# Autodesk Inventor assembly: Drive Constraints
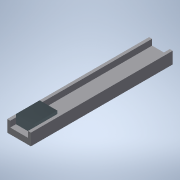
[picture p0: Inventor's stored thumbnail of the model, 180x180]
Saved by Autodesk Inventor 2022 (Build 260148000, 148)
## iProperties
Created: 2014-03
Part Number: Drive Constraints
Document SubType Name: Assembly
Designer: John
Author: John
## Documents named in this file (3)
- C:\Users\helfenj\Desktop\Ex_Files_Autodesk_Inventor_2022_Essential_Training\Exercise Files\12_Using constraints to position parts\12_04\Drive Constraints.iam
- C:\Users\helfenj\Desktop\Ex_Files_Autodesk_Inventor_2022_Essential_Training\Exercise Files\12_Using constraints to position parts\12_04\Base.ipt
- C:\Users\helfenj\Desktop\Ex_Files_Autodesk_Inventor_2022_Essential_Training\Exercise Files\12_Using constraints to position parts\12_04\Slide.ipt
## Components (2 placed, 2 different names)
1. Base:1 — Mate:1, Mate:2
2. Slide:1 — Mate:1, Mate:2
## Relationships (2: Mate 2)
- Mate:1: Base:1 ↔ Slide:1
- Mate:2: Base:1 ↔ Slide:1
